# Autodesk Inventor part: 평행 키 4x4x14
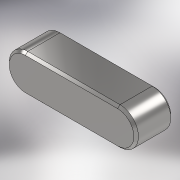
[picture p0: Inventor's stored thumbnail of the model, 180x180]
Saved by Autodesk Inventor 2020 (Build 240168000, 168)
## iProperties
Created: 2024-12
Part Number: 평행 키 4x4x14
Material: 강철, 연강
Description: 키 및 해당 키홈
Document SubType Name: Modeling
Designer: 1강의실14
Density: 7.85 g/cm^3
Appearance: 기본값
Author: jhkim
Sending System: Autodesk Inventor 2025
Preprocessor: ST-DEVELOPER v20
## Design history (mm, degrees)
feature "Solid1"
node "솔리드1"
